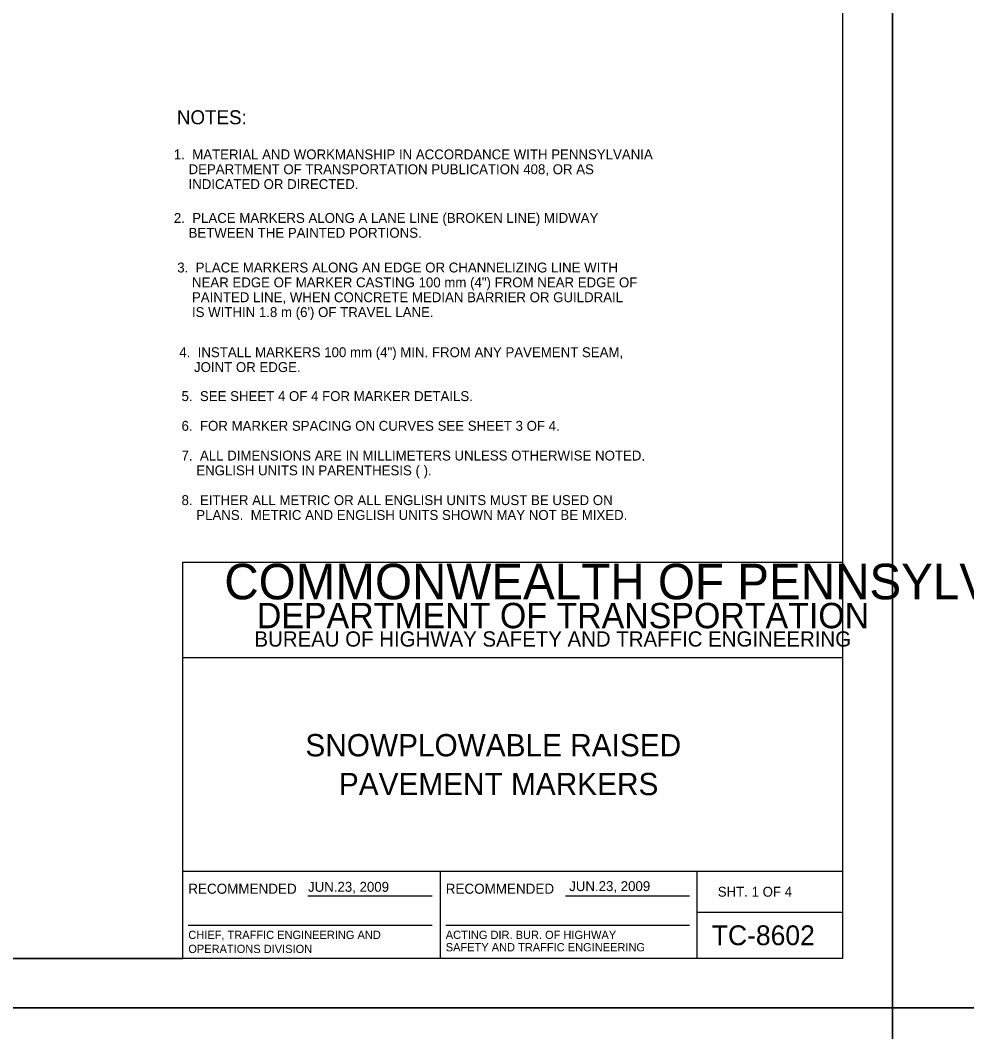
# Model space of a CAD drawing. Extents: x 639362 to 641108, y 298458 to 299646.
# Drawn here: x 639939.1 to 640225.9, y 299044.4 to 299350.7 of the extents above; entities that cross this region are included whole.
import ezdxf

# ---------------------------------------------------------------- set-up
doc = ezdxf.new("R2010")
doc.units = 0
for name, color, linetype in [('1', 7, 'Continuous'), ('2', 7, 'Continuous'), ('PLT-BNDY', 7, 'Continuous')]:
    doc.layers.add(name, color=color, linetype=linetype)

msp = doc.modelspace()

# ---------------------------------------------------------------- linework, layer by layer
at = {"layer": '1'}
for p, q in [((640188.31, 299066.63), (640188.31, 299630.63)), ((639988.31, 299066.63), (639988.31, 299186.63)), ((639988.31, 299186.63), (640188.31, 299186.63)), ((640188.31, 299157.63), (639988.31, 299157.63)), ((639988.31, 299093), (640188.31, 299093)), ((640066.31, 299093), (640066.31, 299066.63)), ((640144.19, 299066.63), (640144.19, 299093)), ((640026.24, 299085.57), (640063.87, 299085.57)), ((640104.24, 299085.57), (640141.87, 299085.57)), ((640144.19, 299080.63), (640188.31, 299080.63)), ((639989.99, 299076.68), (640063.87, 299076.68)), ((640067.99, 299076.68), (640141.87, 299076.68)), ((640188.31, 299066.63), (639402.31, 299066.63)), ((639402.31, 299066.63), (639988.31, 299066.63))]:
    msp.add_line(p, q, dxfattribs=at)
at = {"layer": 'PLT-BNDY'}
for points in [[(639362.31, 299645.63), (640203.31, 299645.63), (640203.31, 299051.63), (639362.31, 299051.63)], [(640203.31, 299645.63), (641044.31, 299645.63), (641044.31, 299051.63), (640203.31, 299051.63)], [(639362.31, 299051.63), (640203.31, 299051.63), (640203.31, 298457.63), (639362.31, 298457.63)], [(640203.31, 299051.63), (641044.31, 299051.63), (641044.31, 298457.63), (640203.31, 298457.63)]]:
    msp.add_lwpolyline(points, close=True, dxfattribs=at)

# ---------------------------------------------------------------- texts
at = {"layer": '1'}
for s, height, p in [('COMMONWEALTH OF PENNSYLVANIA', 10.7828, (640000.9, 299175.36)), ('DEPARTMENT OF TRANSPORTATION', 7.6837, (640010.76, 299166.61)), ('BUREAU OF HIGHWAY SAFETY AND TRAFFIC ENGINEERING', 4.6253, (640010.04, 299161.04)), ('SNOWPLOWABLE RAISED', 6.75, (640025.46, 299127.81)), ('PAVEMENT MARKERS', 6.75, (640035.61, 299116.06)), ('RECOMMENDED', 3.048, (639989.99, 299086.2)), ('RECOMMENDED', 3.048, (640067.99, 299086.2)), ('SHT. 1 OF 4', 3, (640150.4, 299085.31)), ('CHIEF, TRAFFIC ENGINEERING AND', 2.5, (639989.99, 299072.51)), ('ACTING DIR. BUR. OF HIGHWAY', 2.5, (640067.99, 299072.51)), ('TC-8602', 6, (640148.6, 299070.63)), ('SAFETY AND TRAFFIC ENGINEERING', 2.5, (640067.99, 299068.76)), ('OPERATIONS DIVISION', 2.5, (639989.99, 299068.26))]:
    msp.add_text(s, height=height, dxfattribs=at).set_placement(p)
for p in [(640026.27, 299086.8), (640105.4, 299087.01)]:
    msp.add_text('JUN.23, 2009', height=3, rotation=360, dxfattribs=at).set_placement(p)
at = {"layer": '2'}
for s, height, p in [('NOTES:', 4.25, (639986.54, 299319.21)), ('1.  MATERIAL AND WORKMANSHIP IN ACCORDANCE WITH PENNSYLVANIA', 3, (639985.6, 299308.6)), ('    DEPARTMENT OF TRANSPORTATION PUBLICATION 408, OR AS', 3, (639985.6, 299304.1)), ('    INDICATED OR DIRECTED.', 3, (639985.6, 299299.6)), ('2.  PLACE MARKERS ALONG A LANE LINE (BROKEN LINE) MIDWAY', 3, (639985.6, 299289.35)), ('    BETWEEN THE PAINTED PORTIONS.', 3, (639985.6, 299284.85)), ('3.  PLACE MARKERS ALONG AN EDGE OR CHANNELIZING LINE WITH ', 3, (639986.64, 299274.34)), ('    NEAR EDGE OF MARKER CASTING 100 mm (4") FROM NEAR EDGE OF ', 3, (639986.64, 299269.84)), ('    PAINTED LINE, WHEN CONCRETE MEDIAN BARRIER OR GUILDRAIL', 3, (639986.64, 299265.34)), ("    IS WITHIN 1.8 m (6') OF TRAVEL LANE.", 3, (639986.64, 299260.84)), ('4.  INSTALL MARKERS 100 mm (4") MIN. FROM ANY PAVEMENT SEAM,', 3, (639987.25, 299248.69)), ('    JOINT OR EDGE.', 3, (639987.25, 299244.19)), ('5.  SEE SHEET 4 OF 4 FOR MARKER DETAILS.', 3, (639987.94, 299235.4)), ('6.  FOR MARKER SPACING ON CURVES SEE SHEET 3 OF 4.', 3, (639987.94, 299226.4)), ('7.  ALL DIMENSIONS ARE IN MILLIMETERS UNLESS OTHERWISE NOTED.', 3, (639987.94, 299217.4)), ('    ENGLISH UNITS IN PARENTHESIS ( ).', 3, (639987.94, 299212.9)), ('8.  EITHER ALL METRIC OR ALL ENGLISH UNITS MUST BE USED ON', 3, (639987.94, 299203.9)), ('    PLANS.  METRIC AND ENGLISH UNITS SHOWN MAY NOT BE MIXED.', 3, (639987.94, 299199.4))]:
    msp.add_text(s, height=height, dxfattribs=at).set_placement(p)

doc.saveas('drawing.dxf')
